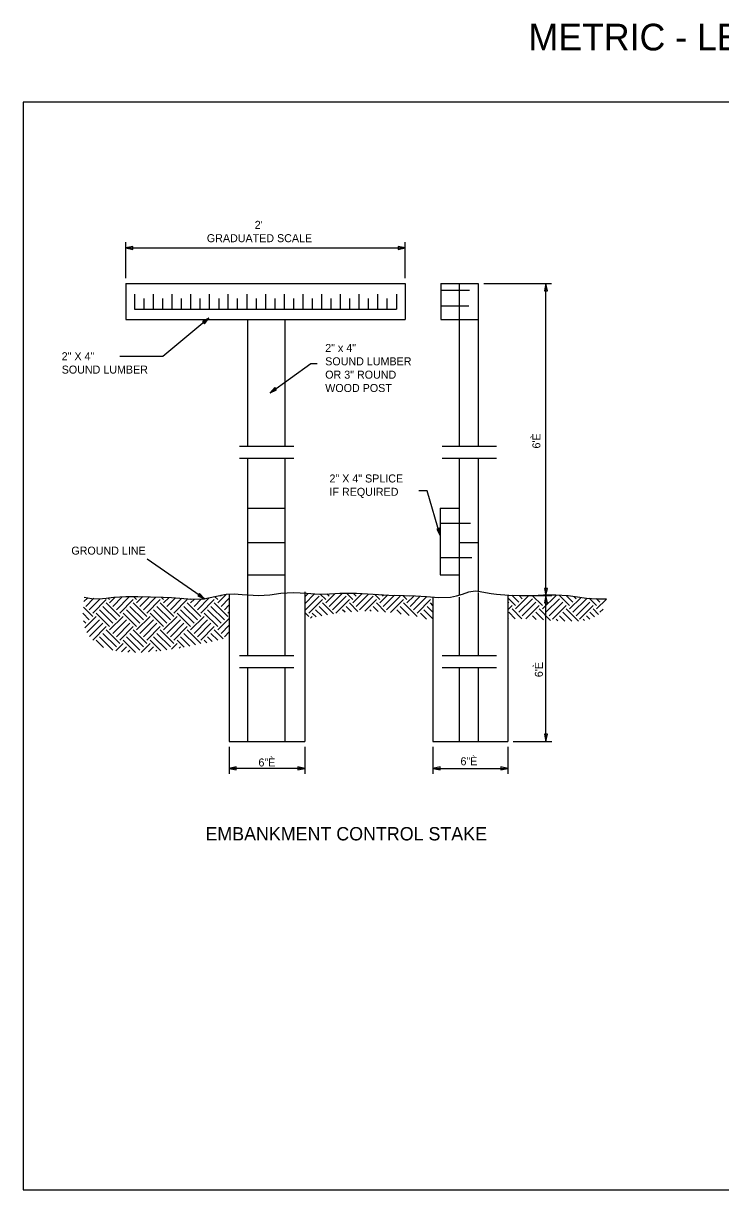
# Model space of a CAD drawing. Extents: x -439.1 to -407.9, y -458.1 to -436.2.
# Drawn here: x -439.11 to -426.04, y -458.05 to -436.2 of the extents above; entities that cross this region are included whole.
import ezdxf

# ---------------------------------------------------------------- set-up
doc = ezdxf.new("R2010")
doc.units = 0
for name, color, linetype in [('Bridge-Named Boundary', 7, 'Continuous'), ('Default', 7, 'Continuous'), ('Level 4', 7, 'Continuous'), ('Level 46', 7, 'Continuous')]:
    doc.layers.add(name, color=color, linetype=linetype)

msp = doc.modelspace()

# ---------------------------------------------------------------- linework, layer by layer
at = {"layer": 'Bridge-Named Boundary'}
msp.add_lwpolyline([(-439.109, -458.051), (-407.859, -458.051), (-407.859, -437.676), (-439.109, -437.676)], close=True, dxfattribs=at)
at = {"layer": 'Default'}
for p, q in [((-430.479, -441.075), (-429.212, -441.075)), ((-429.316, -446.921), (-429.316, -441.075)), ((-435.731, -441.807), (-435.659, -441.747)), ((-435.659, -441.747), (-435.731, -441.807)), ((-435.659, -441.747), (-435.675, -441.747)), ((-435.675, -441.747), (-435.659, -441.747)), ((-435.63, -441.722), (-435.659, -441.747)), ((-435.659, -441.747), (-435.63, -441.722)), ((-435.649, -441.747), (-435.659, -441.747)), ((-435.659, -441.747), (-435.649, -441.747)), ((-433.723, -442.573), (-433.603, -442.573)), ((-434.485, -443.119), (-434.378, -443.042)), ((-434.378, -443.042), (-434.485, -443.119)), ((-435.057, -444.117), (-434.039, -444.117)), ((-431.261, -444.117), (-430.243, -444.117)), ((-435.057, -444.342), (-434.039, -444.342)), ((-431.261, -444.342), (-430.243, -444.342)), ((-431.539, -444.958), (-431.7, -444.958)), ((-431.299, -445.791), (-431.539, -444.958)), ((-434.909, -445.281), (-434.207, -445.281)), ((-431.299, -445.564), (-430.732, -445.564)), ((-431.336, -445.664), (-431.299, -445.791)), ((-431.299, -445.791), (-431.336, -445.664)), ((-434.909, -445.922), (-434.207, -445.922)), ((-430.941, -445.922), (-430.583, -445.922)), ((-435.717, -446.979), (-436.787, -446.235)), ((-431.299, -446.205), (-430.702, -446.205)), ((-435.826, -446.903), (-435.717, -446.979)), ((-435.826, -446.903), (-435.717, -446.979)), ((-435.717, -446.979), (-435.826, -446.903)), ((-435.467, -447.058), (-435.301, -446.892)), ((-435.251, -446.891), (-435.251, -449.651)), ((-434.207, -446.862), (-434.207, -446.869)), ((-434.207, -446.869), (-434.207, -448.04)), ((-433.835, -446.847), (-433.835, -449.651)), ((-433.835, -446.944), (-433.769, -446.879)), ((-433.835, -447.071), (-433.651, -446.887)), ((-433.442, -446.994), (-433.545, -446.891)), ((-433.442, -447.058), (-433.264, -446.88)), ((-433.378, -446.931), (-433.423, -446.886)), ((-433.378, -447.121), (-433.135, -446.878)), ((-432.935, -446.994), (-433.05, -446.88)), ((-432.935, -447.058), (-432.764, -446.887)), ((-432.872, -446.931), (-432.92, -446.883)), ((-432.872, -447.121), (-432.641, -446.89)), ((-432.429, -446.994), (-432.53, -446.893)), ((-432.429, -447.058), (-432.277, -446.906)), ((-432.365, -446.931), (-432.397, -446.9)), ((-430.583, -446.862), (-430.583, -448.04)), ((-437.973, -447.032), (-437.9, -446.959)), ((-437.936, -447.121), (-437.786, -446.971)), ((-437.873, -447.184), (-437.666, -446.978)), ((-437.809, -447.247), (-437.556, -446.994)), ((-437.366, -447.374), (-437.62, -447.121)), ((-437.303, -447.311), (-437.556, -447.058)), ((-437.493, -446.994), (-437.524, -446.963)), ((-437.493, -447.058), (-437.386, -446.95)), ((-437.43, -447.121), (-437.255, -446.946)), ((-437.366, -447.184), (-437.124, -446.942)), ((-437.303, -447.247), (-437.05, -446.994)), ((-436.86, -447.374), (-437.113, -447.121)), ((-436.797, -447.311), (-437.05, -447.058)), ((-436.987, -446.994), (-437.042, -446.939)), ((-436.987, -447.058), (-436.868, -446.939)), ((-436.923, -447.121), (-436.746, -446.943)), ((-436.86, -447.184), (-436.623, -446.947)), ((-436.797, -447.247), (-436.543, -446.994)), ((-436.354, -447.374), (-436.607, -447.121)), ((-436.29, -447.311), (-436.543, -447.058)), ((-436.48, -446.994), (-436.524, -446.95)), ((-436.48, -447.058), (-436.379, -446.957)), ((-436.417, -447.121), (-436.258, -446.962)), ((-436.354, -447.184), (-436.139, -446.969)), ((-436.29, -447.247), (-436.037, -446.994)), ((-435.847, -447.374), (-436.1, -447.121)), ((-435.784, -447.311), (-436.037, -447.058)), ((-435.974, -446.994), (-435.986, -446.982)), ((-435.974, -447.058), (-435.9, -446.984)), ((-435.91, -447.121), (-435.771, -446.982)), ((-435.847, -447.184), (-435.625, -446.962)), ((-435.784, -447.247), (-435.531, -446.994)), ((-435.341, -447.374), (-435.594, -447.121)), ((-435.277, -447.311), (-435.531, -447.058)), ((-435.467, -446.994), (-435.524, -446.937)), ((-435.404, -446.931), (-435.423, -446.912)), ((-435.404, -447.121), (-435.251, -446.968)), ((-435.341, -447.184), (-435.251, -447.095)), ((-434.909, -446.908), (-434.909, -448.04)), ((-433.821, -447.184), (-433.568, -446.931)), ((-433.758, -447.247), (-433.505, -446.994)), ((-433.409, -447.28), (-433.568, -447.121)), ((-433.298, -447.264), (-433.505, -447.058)), ((-433.315, -447.184), (-433.062, -446.931)), ((-433.252, -447.247), (-432.998, -446.994)), ((-432.96, -447.223), (-433.062, -447.121)), ((-432.839, -447.217), (-432.998, -447.058)), ((-432.809, -447.184), (-432.555, -446.931)), ((-432.709, -447.211), (-432.492, -446.994)), ((-432.457, -447.219), (-432.555, -447.121)), ((-432.322, -447.228), (-432.492, -447.058)), ((-432.365, -447.121), (-432.156, -446.912)), ((-432.302, -447.184), (-432.049, -446.931)), ((-432.227, -447.235), (-431.986, -446.994)), ((-431.878, -447.292), (-432.049, -447.121)), ((-431.922, -446.994), (-431.997, -446.92)), ((-431.732, -447.311), (-431.986, -447.058)), ((-431.922, -447.058), (-431.793, -446.928)), ((-431.859, -446.931), (-431.865, -446.925)), ((-431.859, -447.121), (-431.67, -446.932)), ((-431.796, -447.184), (-431.548, -446.937)), ((-431.732, -447.247), (-431.479, -446.994)), ((-431.433, -447.23), (-431.543, -447.121)), ((-431.433, -447.104), (-431.479, -447.058)), ((-431.433, -446.947), (-431.433, -449.651)), ((-430.941, -446.951), (-430.941, -448.04)), ((-430.032, -446.921), (-430.032, -449.651)), ((-429.887, -447.106), (-430.032, -446.961)), ((-430.032, -447.061), (-430.013, -447.043)), ((-430.032, -447.188), (-429.95, -447.106)), ((-429.823, -447.043), (-429.952, -446.914)), ((-429.887, -447.169), (-429.635, -446.918)), ((-429.823, -447.233), (-429.57, -446.98)), ((-429.76, -446.98), (-429.82, -446.92)), ((-429.76, -447.296), (-429.507, -447.043)), ((-429.694, -447.357), (-429.443, -447.106)), ((-429.674, -446.921), (-429.212, -446.921)), ((-429.674, -446.921), (-429.208, -446.921)), ((-429.38, -447.106), (-429.571, -446.916)), ((-429.38, -447.169), (-429.127, -446.916)), ((-429.317, -447.233), (-429.064, -446.98)), ((-429.316, -449.651), (-429.316, -446.921)), ((-429.253, -447.296), (-429, -447.043)), ((-429.19, -447.359), (-428.937, -447.106)), ((-428.874, -447.106), (-429.07, -446.91)), ((-428.81, -447.043), (-428.934, -446.919)), ((-428.874, -447.169), (-428.658, -446.954)), ((-428.81, -447.233), (-428.557, -446.98)), ((-428.747, -446.98), (-428.792, -446.935)), ((-428.747, -447.296), (-428.494, -447.043)), ((-428.684, -447.359), (-428.431, -447.106)), ((-428.367, -447.106), (-428.505, -446.968)), ((-428.304, -447.043), (-428.373, -446.973)), ((-428.367, -447.169), (-428.184, -446.986)), ((-428.241, -446.98), (-428.241, -446.979)), ((-437.873, -447.374), (-437.995, -447.252)), ((-437.809, -447.311), (-437.984, -447.137)), ((-437.957, -447.522), (-437.746, -447.311)), ((-437.493, -447.501), (-437.746, -447.247)), ((-437.43, -447.437), (-437.683, -447.184)), ((-437.493, -447.564), (-437.24, -447.311)), ((-436.987, -447.501), (-437.24, -447.247)), ((-436.923, -447.437), (-437.176, -447.184)), ((-436.987, -447.564), (-436.733, -447.311)), ((-436.48, -447.501), (-436.733, -447.247)), ((-436.417, -447.437), (-436.67, -447.184)), ((-436.48, -447.564), (-436.227, -447.311)), ((-435.974, -447.501), (-436.227, -447.247)), ((-435.91, -447.437), (-436.164, -447.184)), ((-435.974, -447.564), (-435.721, -447.311)), ((-435.467, -447.501), (-435.721, -447.247)), ((-435.404, -447.437), (-435.657, -447.184)), ((-435.277, -447.247), (-435.251, -447.221)), ((-433.758, -447.311), (-433.835, -447.234)), ((-433.725, -447.341), (-433.695, -447.311)), ((-433.622, -447.32), (-433.695, -447.247)), ((-433.517, -447.299), (-433.632, -447.184)), ((-433.188, -447.248), (-433.188, -447.247)), ((-433.077, -447.233), (-433.125, -447.184)), ((-432.592, -447.211), (-432.619, -447.184)), ((-432.029, -447.267), (-432.112, -447.184)), ((-431.556, -447.361), (-431.669, -447.247)), ((-431.433, -447.357), (-431.606, -447.184)), ((-430.018, -447.354), (-430.032, -447.341)), ((-429.891, -447.354), (-430.013, -447.233)), ((-429.765, -447.354), (-429.95, -447.169)), ((-429.498, -447.368), (-429.57, -447.296)), ((-429.363, -447.376), (-429.507, -447.233)), ((-429.229, -447.384), (-429.443, -447.169)), ((-428.96, -447.4), (-429.064, -447.296)), ((-428.832, -447.401), (-429, -447.233)), ((-428.705, -447.401), (-428.937, -447.169)), ((-428.494, -447.359), (-428.557, -447.296)), ((-428.407, -447.32), (-428.494, -447.233)), ((-428.328, -447.272), (-428.431, -447.169)), ((-428.304, -447.233), (-428.246, -447.175)), ((-437.936, -447.437), (-437.98, -447.394)), ((-437.92, -447.611), (-437.683, -447.374)), ((-437.868, -447.686), (-437.62, -447.437)), ((-437.809, -447.754), (-437.556, -447.501)), ((-437.43, -447.627), (-437.176, -447.374)), ((-437.366, -447.691), (-437.113, -447.437)), ((-437.303, -447.754), (-437.05, -447.501)), ((-436.923, -447.627), (-436.67, -447.374)), ((-436.86, -447.691), (-436.607, -447.437)), ((-436.797, -447.754), (-436.543, -447.501)), ((-436.417, -447.627), (-436.164, -447.374)), ((-436.354, -447.691), (-436.1, -447.437)), ((-436.29, -447.754), (-436.037, -447.501)), ((-435.91, -447.627), (-435.657, -447.374)), ((-435.847, -447.691), (-435.594, -447.437)), ((-435.784, -447.754), (-435.531, -447.501)), ((-435.467, -447.564), (-435.251, -447.348)), ((-435.404, -447.627), (-435.251, -447.475)), ((-433.832, -447.363), (-433.835, -447.361)), ((-429.632, -447.36), (-429.633, -447.359)), ((-429.094, -447.392), (-429.127, -447.359)), ((-428.593, -447.387), (-428.62, -447.359)), ((-437.609, -447.891), (-437.746, -447.754)), ((-437.432, -447.941), (-437.683, -447.691)), ((-437.366, -447.881), (-437.62, -447.627)), ((-437.303, -447.817), (-437.556, -447.564)), ((-437.008, -447.986), (-437.24, -447.754)), ((-436.923, -447.944), (-437.176, -447.691)), ((-436.86, -447.881), (-437.113, -447.627)), ((-436.797, -447.817), (-437.05, -447.564)), ((-436.532, -447.955), (-436.733, -447.754)), ((-436.422, -447.939), (-436.67, -447.691)), ((-436.354, -447.881), (-436.607, -447.627)), ((-436.29, -447.817), (-436.543, -447.564)), ((-436.093, -447.887), (-436.227, -447.754)), ((-435.988, -447.866), (-436.164, -447.691)), ((-435.882, -447.845), (-436.1, -447.627)), ((-435.784, -447.817), (-436.037, -447.564)), ((-435.672, -447.803), (-435.721, -447.754)), ((-435.569, -447.779), (-435.657, -447.691)), ((-435.466, -447.755), (-435.594, -447.627)), ((-435.363, -447.732), (-435.531, -447.564)), ((-435.341, -447.691), (-435.251, -447.601)), ((-437.377, -447.954), (-437.24, -447.817)), ((-437.27, -447.974), (-437.176, -447.881)), ((-437.149, -447.98), (-437.113, -447.944)), ((-436.901, -447.985), (-436.733, -447.817)), ((-436.764, -447.974), (-436.67, -447.881)), ((-436.627, -447.964), (-436.607, -447.944)), ((-436.335, -447.926), (-436.227, -447.817)), ((-436.186, -447.903), (-436.164, -447.881)), ((-435.057, -448.04), (-434.039, -448.04)), ((-431.261, -448.04), (-430.243, -448.04)), ((-435.057, -448.264), (-434.039, -448.264)), ((-434.909, -448.264), (-434.909, -449.651)), ((-434.207, -448.264), (-434.207, -449.651)), ((-431.261, -448.264), (-430.243, -448.264)), ((-430.941, -448.264), (-430.941, -449.651)), ((-430.583, -448.264), (-430.583, -449.651)), ((-435.251, -449.651), (-433.835, -449.651)), ((-431.433, -449.651), (-430.032, -449.651)), ((-429.927, -449.651), (-429.208, -449.651)), ((-435.251, -449.755), (-435.251, -450.262)), ((-433.835, -449.755), (-433.835, -450.262)), ((-431.433, -449.755), (-431.433, -450.262)), ((-430.032, -449.755), (-430.032, -450.262)), ((-433.835, -450.158), (-435.251, -450.158)), ((-431.433, -450.158), (-430.032, -450.158))]:
    msp.add_line(p, q, dxfattribs=at)
for points in [[(-437.058, -440.377), (-437.19, -440.404), (-437.058, -440.432)], [(-432.087, -440.432), (-431.955, -440.404), (-432.087, -440.377)], [(-429.288, -441.207), (-429.316, -441.075), (-429.343, -441.207)], [(-435.714, -441.828), (-435.63, -441.722), (-435.749, -441.786)], [(-434.393, -443.019), (-434.485, -443.119), (-434.362, -443.064)], [(-431.362, -445.672), (-431.299, -445.791), (-431.309, -445.657)], [(-435.841, -446.926), (-435.717, -446.979), (-435.81, -446.881)], [(-429.343, -446.789), (-429.316, -446.921), (-429.288, -446.789)], [(-429.288, -447.054), (-429.316, -446.921), (-429.343, -447.054)], [(-429.343, -449.519), (-429.316, -449.651), (-429.288, -449.519)], [(-435.119, -450.13), (-435.251, -450.158), (-435.119, -450.185)], [(-433.967, -450.185), (-433.835, -450.158), (-433.967, -450.13)], [(-431.301, -450.13), (-431.433, -450.158), (-431.301, -450.185)], [(-430.164, -450.185), (-430.032, -450.158), (-430.164, -450.13)]]:
    msp.add_lwpolyline(points, close=True, dxfattribs=at)
for points in [[(-435.675, -441.747), (-435.749, -441.786), (-435.731, -441.807)], [(-435.731, -441.807), (-435.714, -441.828)], [(-435.714, -441.828), (-435.649, -441.747)], [(-435.63, -441.722), (-435.675, -441.747)], [(-435.649, -441.747), (-435.63, -441.722)], [(-434.378, -443.042), (-434.393, -443.019), (-434.485, -443.119)], [(-434.485, -443.119), (-434.362, -443.064), (-434.378, -443.042)], [(-431.336, -445.664), (-431.362, -445.672), (-431.299, -445.791)], [(-431.299, -445.791), (-431.309, -445.657), (-431.336, -445.664)], [(-435.826, -446.903), (-435.841, -446.926), (-435.717, -446.979)], [(-435.717, -446.979), (-435.81, -446.881), (-435.826, -446.903)], [(-435.717, -446.979), (-435.81, -446.881), (-435.826, -446.903)]]:
    msp.add_lwpolyline(points, dxfattribs=at)
at = {"layer": 'Level 4'}
for p, q in [((-437.19, -440.971), (-437.19, -440.297)), ((-431.955, -440.971), (-431.955, -440.297)), ((-437.19, -440.404), (-431.955, -440.404)), ((-437.19, -441.075), (-437.19, -441.747)), ((-437.19, -441.075), (-431.956, -441.075)), ((-431.956, -441.075), (-431.956, -441.747)), ((-431.284, -441.075), (-430.583, -441.075)), ((-431.284, -441.075), (-431.284, -441.747)), ((-431.284, -441.194), (-430.748, -441.194)), ((-430.941, -441.075), (-430.941, -444.117)), ((-430.583, -441.075), (-430.583, -444.117)), ((-437.026, -441.269), (-437.026, -441.552)), ((-436.851, -441.352), (-436.851, -441.552)), ((-436.675, -441.269), (-436.675, -441.552)), ((-436.5, -441.352), (-436.5, -441.552)), ((-436.325, -441.269), (-436.325, -441.552)), ((-436.15, -441.352), (-436.15, -441.552)), ((-435.975, -441.269), (-435.975, -441.552)), ((-435.799, -441.352), (-435.799, -441.552)), ((-435.624, -441.269), (-435.624, -441.552)), ((-435.448, -441.352), (-435.448, -441.552)), ((-435.274, -441.269), (-435.274, -441.552)), ((-435.099, -441.352), (-435.099, -441.552)), ((-434.923, -441.269), (-434.923, -441.552)), ((-434.748, -441.352), (-434.748, -441.552)), ((-434.572, -441.269), (-434.572, -441.552)), ((-434.398, -441.352), (-434.398, -441.552)), ((-434.223, -441.269), (-434.223, -441.552)), ((-434.047, -441.352), (-434.047, -441.552)), ((-433.872, -441.269), (-433.872, -441.552)), ((-433.696, -441.352), (-433.696, -441.552)), ((-433.522, -441.269), (-433.522, -441.552)), ((-433.346, -441.352), (-433.346, -441.552)), ((-433.171, -441.269), (-433.171, -441.552)), ((-432.995, -441.352), (-432.995, -441.552)), ((-432.82, -441.269), (-432.82, -441.552)), ((-432.646, -441.352), (-432.646, -441.552)), ((-432.47, -441.269), (-432.47, -441.552)), ((-432.295, -441.352), (-432.295, -441.552)), ((-432.119, -441.269), (-432.119, -441.552)), ((-437.026, -441.552), (-432.119, -441.552)), ((-431.284, -441.493), (-430.762, -441.493)), ((-437.19, -441.747), (-431.956, -441.747)), ((-435.63, -441.722), (-436.492, -442.441)), ((-434.909, -441.747), (-434.909, -444.117)), ((-434.207, -441.747), (-434.207, -444.117)), ((-431.284, -441.747), (-430.583, -441.747)), ((-436.492, -442.441), (-437.298, -442.441)), ((-434.485, -443.119), (-433.723, -442.573)), ((-434.909, -444.342), (-434.909, -446.908)), ((-434.207, -444.342), (-434.207, -446.869)), ((-430.941, -444.342), (-430.941, -446.912)), ((-430.583, -444.342), (-430.583, -446.835)), ((-431.299, -445.281), (-430.941, -445.281)), ((-431.299, -445.281), (-431.299, -446.533)), ((-434.909, -446.533), (-434.207, -446.533)), ((-431.299, -446.533), (-430.941, -446.533))]:
    msp.add_line(p, q, dxfattribs=at)
msp.add_lwpolyline([(-437.966, -446.951), (-437.832, -446.974), (-437.697, -446.981), (-437.555, -446.97), (-437.414, -446.951), (-437.19, -446.936), (-436.966, -446.936), (-436.728, -446.943), (-436.489, -446.951), (-436.333, -446.957), (-436.176, -446.966), (-435.951, -446.985), (-435.729, -446.981), (-435.52, -446.936), (-435.311, -446.892), (-435.159, -446.886), (-435.006, -446.898), (-434.7, -446.921), (-434.491, -446.905), (-434.282, -446.877), (-434.163, -446.866), (-434.043, -446.862), (-433.805, -446.876), (-433.566, -446.892), (-433.372, -446.887), (-433.178, -446.877), (-432.865, -446.876), (-432.552, -446.892), (-432.261, -446.909), (-431.97, -446.921), (-431.762, -446.926), (-431.553, -446.936), (-431.328, -446.956), (-431.105, -446.951), (-430.993, -446.927), (-430.882, -446.892), (-430.763, -446.852), (-430.643, -446.832), (-430.546, -446.842), (-430.449, -446.862), (-430.345, -446.879), (-430.24, -446.892), (-430.01, -446.913), (-429.778, -446.921), (-429.569, -446.916), (-429.36, -446.907), (-429.129, -446.906), (-428.898, -446.921), (-428.727, -446.944), (-428.555, -446.966), (-428.369, -446.979), (-428.182, -446.981)], dxfattribs=at)

# ---------------------------------------------------------------- texts
at = {"layer": 'Default'}
for p in [(-429.42, -444.164), (-429.374, -448.448)]:
    msp.add_text("6'È", height=0.15, rotation=90, dxfattribs=at).set_placement(p)
for s, p in [('2" X 4" SPLICE', (-433.372, -444.8)), ('IF REQUIRED', (-433.372, -445.05)), ('GROUND LINE', (-438.209, -446.152)), ('6"È', (-434.703, -450.121)), ('6"È', (-430.917, -450.099))]:
    msp.add_text(s, height=0.15, dxfattribs=at).set_placement(p)
at = {"layer": 'Level 4'}
for s, height, p in [("2' ", 0.15, (-434.773, -440.048)), ('GRADUATED SCALE', 0.15, (-435.67, -440.298)), ('2" x 4"', 0.15, (-433.452, -442.355)), ('2" X 4" ', 0.15, (-438.39, -442.51)), ('SOUND LUMBER ', 0.15, (-433.452, -442.605)), ('SOUND LUMBER', 0.15, (-438.39, -442.76)), ('OR 3" ROUND ', 0.15, (-433.452, -442.855)), ('WOOD POST', 0.15, (-433.452, -443.105)), ('EMBANKMENT CONTROL STAKE', 0.25, (-435.696, -451.507))]:
    msp.add_text(s, height=height, dxfattribs=at).set_placement(p)
at = {"layer": 'Level 46'}
msp.add_text('METRIC - LEVEL 46 - GREEN', height=0.5, dxfattribs=at).set_placement((-429.642, -436.705))

doc.saveas('drawing.dxf')
